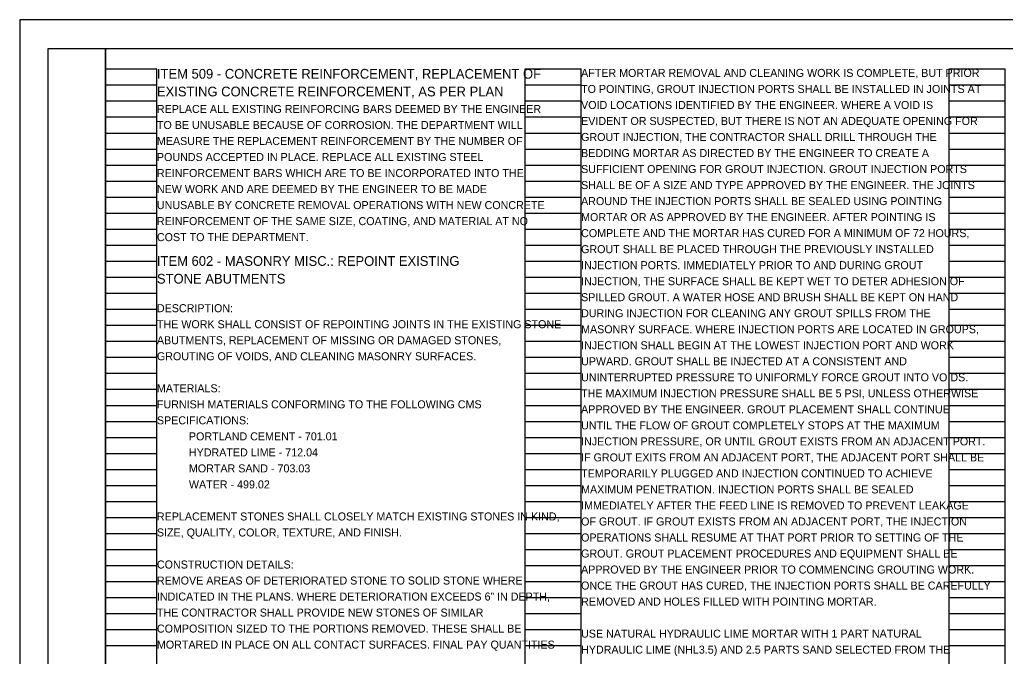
# Model space of a CAD drawing. Extents: x 0 to 59.1, y 0 to 43.6.
# Drawn here: x 0 to 17.24, y 10.87 to 22 of the extents above; entities that cross this region are included whole.
import ezdxf

# ---------------------------------------------------------------- set-up
doc = ezdxf.new("R2010")
doc.units = 0
for name, color, linetype in [('BR_P_Gen_Text', 7, 'Continuous'), ('SH_Border', 7, 'Continuous'), ('SH_Cut_Line', 7, 'Continuous'), ('SH_Data', 7, 'Continuous'), ('SH_Text', 7, 'Continuous')]:
    doc.layers.add(name, color=color, linetype=linetype)

msp = doc.modelspace()

# ---------------------------------------------------------------- linework, layer by layer
at = {"layer": 'SH_Border'}
for points in [[(0.5, 21.5), (1.5, 21.5), (1.5, 0.5), (0.5, 0.5)], [(1.5, 21.5), (33.5, 21.5), (33.5, 0.5), (1.5, 0.5)]]:
    msp.add_lwpolyline(points, close=True, dxfattribs=at)
at = {"layer": 'SH_Cut_Line'}
msp.add_lwpolyline([(0, 0), (34, 0), (34, 22), (0, 22)], close=True, dxfattribs=at)
at = {"layer": 'SH_Data'}
for p, q in [((1.5, 0.98), (1.5, 21.14)), ((1.5, 21.14), (2.4, 21.14)), ((2.4, 0.98), (2.4, 21.14)), ((8.84, 0.98), (8.84, 21.14)), ((8.84, 21.14), (9.82, 21.14)), ((9.82, 0.98), (9.82, 21.14)), ((16.26, 0.98), (16.26, 21.14)), ((16.26, 21.14), (17.24, 21.14)), ((17.24, 0.98), (17.24, 21.14)), ((1.5, 20.86), (2.4, 20.86)), ((8.84, 20.86), (9.82, 20.86)), ((16.26, 20.86), (17.24, 20.86)), ((1.5, 20.58), (2.4, 20.58)), ((8.84, 20.58), (9.82, 20.58)), ((16.26, 20.58), (17.24, 20.58)), ((1.5, 20.3), (2.4, 20.3)), ((8.84, 20.3), (9.82, 20.3)), ((16.26, 20.3), (17.24, 20.3)), ((1.5, 20.02), (2.4, 20.02)), ((8.84, 20.02), (9.82, 20.02)), ((16.26, 20.02), (17.24, 20.02)), ((1.5, 19.74), (2.4, 19.74)), ((8.84, 19.74), (9.82, 19.74)), ((16.26, 19.74), (17.24, 19.74)), ((1.5, 19.46), (2.4, 19.46)), ((8.84, 19.46), (9.82, 19.46)), ((16.26, 19.46), (17.24, 19.46)), ((1.5, 19.18), (2.4, 19.18)), ((8.84, 19.18), (9.82, 19.18)), ((16.26, 19.18), (17.24, 19.18)), ((1.5, 18.9), (2.4, 18.9)), ((8.84, 18.9), (9.82, 18.9)), ((16.26, 18.9), (17.24, 18.9)), ((1.5, 18.62), (2.4, 18.62)), ((8.84, 18.62), (9.82, 18.62)), ((16.26, 18.62), (17.24, 18.62)), ((1.5, 18.34), (2.4, 18.34)), ((8.84, 18.34), (9.82, 18.34)), ((16.26, 18.34), (17.24, 18.34)), ((1.5, 18.06), (2.4, 18.06)), ((8.84, 18.06), (9.82, 18.06)), ((16.26, 18.06), (17.24, 18.06)), ((1.5, 17.78), (2.4, 17.78)), ((8.84, 17.78), (9.82, 17.78)), ((16.26, 17.78), (17.24, 17.78)), ((1.5, 17.5), (2.4, 17.5)), ((8.84, 17.5), (9.82, 17.5)), ((16.26, 17.5), (17.24, 17.5)), ((1.5, 17.22), (2.4, 17.22)), ((8.84, 17.22), (9.82, 17.22)), ((16.26, 17.22), (17.24, 17.22)), ((1.5, 16.94), (2.4, 16.94)), ((8.84, 16.94), (9.82, 16.94)), ((16.26, 16.94), (17.24, 16.94)), ((1.5, 16.66), (2.4, 16.66)), ((8.84, 16.66), (9.82, 16.66)), ((16.26, 16.66), (17.24, 16.66)), ((1.5, 16.38), (2.4, 16.38)), ((8.84, 16.38), (9.82, 16.38)), ((16.26, 16.38), (17.24, 16.38)), ((1.5, 16.1), (2.4, 16.1)), ((8.84, 16.1), (9.82, 16.1)), ((16.26, 16.1), (17.24, 16.1)), ((1.5, 15.82), (2.4, 15.82)), ((8.84, 15.82), (9.82, 15.82)), ((16.26, 15.82), (17.24, 15.82)), ((1.5, 15.54), (2.4, 15.54)), ((8.84, 15.54), (9.82, 15.54)), ((16.26, 15.54), (17.24, 15.54)), ((1.5, 15.26), (2.4, 15.26)), ((8.84, 15.26), (9.82, 15.26)), ((16.26, 15.26), (17.24, 15.26)), ((1.5, 14.98), (2.4, 14.98)), ((8.84, 14.98), (9.82, 14.98)), ((16.26, 14.98), (17.24, 14.98)), ((1.5, 14.7), (2.4, 14.7)), ((8.84, 14.7), (9.82, 14.7)), ((16.26, 14.7), (17.24, 14.7)), ((1.5, 14.42), (2.4, 14.42)), ((8.84, 14.42), (9.82, 14.42)), ((16.26, 14.42), (17.24, 14.42)), ((1.5, 14.14), (2.4, 14.14)), ((8.84, 14.14), (9.82, 14.14)), ((16.26, 14.14), (17.24, 14.14)), ((1.5, 13.86), (2.4, 13.86)), ((8.84, 13.86), (9.82, 13.86)), ((16.26, 13.86), (17.24, 13.86)), ((1.5, 13.58), (2.4, 13.58)), ((8.84, 13.58), (9.82, 13.58)), ((16.26, 13.58), (17.24, 13.58)), ((1.5, 13.3), (2.4, 13.3)), ((8.84, 13.3), (9.82, 13.3)), ((16.26, 13.3), (17.24, 13.3)), ((1.5, 13.02), (2.4, 13.02)), ((8.84, 13.02), (9.82, 13.02)), ((16.26, 13.02), (17.24, 13.02)), ((1.5, 12.74), (2.4, 12.74)), ((8.84, 12.74), (9.82, 12.74)), ((16.26, 12.74), (17.24, 12.74)), ((1.5, 12.46), (2.4, 12.46)), ((8.84, 12.46), (9.82, 12.46)), ((16.26, 12.46), (17.24, 12.46)), ((1.5, 12.18), (2.4, 12.18)), ((8.84, 12.18), (9.82, 12.18)), ((16.26, 12.18), (17.24, 12.18)), ((1.5, 11.9), (2.4, 11.9)), ((8.84, 11.9), (9.82, 11.9)), ((16.26, 11.9), (17.24, 11.9)), ((1.5, 11.62), (2.4, 11.62)), ((8.84, 11.62), (9.82, 11.62)), ((16.26, 11.62), (17.24, 11.62)), ((1.5, 11.34), (2.4, 11.34)), ((8.84, 11.34), (9.82, 11.34)), ((16.26, 11.34), (17.24, 11.34)), ((1.5, 11.06), (2.4, 11.06)), ((8.84, 11.06), (9.82, 11.06)), ((16.26, 11.06), (17.24, 11.06))]:
    msp.add_line(p, q, dxfattribs=at)

# ---------------------------------------------------------------- texts
at = {"layer": 'BR_P_Gen_Text'}
for s, height, p in [('ITEM 509 - CONCRETE REINFORCEMENT, REPLACEMENT OF', 0.17, (2.4, 20.97)), ('EXISTING CONCRETE REINFORCEMENT, AS PER PLAN', 0.17, (2.4, 20.66)), ('REPLACE ALL EXISTING REINFORCING BARS DEEMED BY THE ENGINEER ', 0.14, (2.4, 20.37)), ('TO BE UNUSABLE BECAUSE OF CORROSION. THE DEPARTMENT WILL ', 0.14, (2.4, 20.09)), ('MEASURE THE REPLACEMENT REINFORCEMENT BY THE NUMBER OF ', 0.14, (2.4, 19.81)), ('POUNDS ACCEPTED IN PLACE. REPLACE ALL EXISTING STEEL ', 0.14, (2.4, 19.53)), ('REINFORCEMENT BARS WHICH ARE TO BE INCORPORATED INTO THE ', 0.14, (2.4, 19.25)), ('NEW WORK AND ARE DEEMED BY THE ENGINEER TO BE MADE ', 0.14, (2.4, 18.97)), ('UNUSABLE BY CONCRETE REMOVAL OPERATIONS WITH NEW CONCRETE ', 0.14, (2.4, 18.69)), ('REINFORCEMENT OF THE SAME SIZE, COATING, AND MATERIAL AT NO ', 0.14, (2.4, 18.41)), ('COST TO THE DEPARTMENT.', 0.14, (2.4, 18.13))]:
    msp.add_text(s, height=height, dxfattribs=at).set_placement(p)
at = {"layer": 'SH_Text'}
for s, height, p in [('AFTER MORTAR REMOVAL AND CLEANING WORK IS COMPLETE, BUT PRIOR ', 0.14, (9.82, 21)), ('TO POINTING, GROUT INJECTION PORTS SHALL BE INSTALLED IN JOINTS AT ', 0.14, (9.82, 20.72)), ('VOID LOCATIONS IDENTIFIED BY THE ENGINEER. WHERE A VOID IS ', 0.14, (9.82, 20.44)), ('EVIDENT OR SUSPECTED, BUT THERE IS NOT AN ADEQUATE OPENING FOR ', 0.14, (9.82, 20.16)), ('GROUT INJECTION, THE CONTRACTOR SHALL DRILL THROUGH THE ', 0.14, (9.82, 19.88)), ('BEDDING MORTAR AS DIRECTED BY THE ENGINEER TO CREATE A ', 0.14, (9.82, 19.6)), ('SUFFICIENT OPENING FOR GROUT INJECTION. GROUT INJECTION PORTS ', 0.14, (9.82, 19.32)), ('SHALL BE OF A SIZE AND TYPE APPROVED BY THE ENGINEER. THE JOINTS ', 0.14, (9.82, 19.04)), ('AROUND THE INJECTION PORTS SHALL BE SEALED USING POINTING ', 0.14, (9.82, 18.76)), ('MORTAR OR AS APPROVED BY THE ENGINEER. AFTER POINTING IS ', 0.14, (9.82, 18.48)), ('COMPLETE AND THE MORTAR HAS CURED FOR A MINIMUM OF 72 HOURS, ', 0.14, (9.82, 18.2)), ('GROUT SHALL BE PLACED THROUGH THE PREVIOUSLY INSTALLED ', 0.14, (9.82, 17.92)), ('ITEM 602 - MASONRY MISC.: REPOINT EXISTING', 0.17, (2.4, 17.698)), ('INJECTION PORTS. IMMEDIATELY PRIOR TO AND DURING GROUT ', 0.14, (9.82, 17.64)), ('STONE ABUTMENTS', 0.17, (2.4, 17.388)), ('INJECTION, THE SURFACE SHALL BE KEPT WET TO DETER ADHESION OF ', 0.14, (9.82, 17.36)), ('SPILLED GROUT. A WATER HOSE AND BRUSH SHALL BE KEPT ON HAND ', 0.14, (9.82, 17.08)), ('DESCRIPTION:', 0.14, (2.4, 16.888)), ('DURING INJECTION FOR CLEANING ANY GROUT SPILLS FROM THE ', 0.14, (9.82, 16.8)), ('THE WORK SHALL CONSIST OF REPOINTING JOINTS IN THE EXISTING STONE ', 0.14, (2.4, 16.608)), ('MASONRY SURFACE. WHERE INJECTION PORTS ARE LOCATED IN GROUPS, ', 0.14, (9.82, 16.52)), ('ABUTMENTS, REPLACEMENT OF MISSING OR DAMAGED STONES, ', 0.14, (2.4, 16.328)), ('INJECTION SHALL BEGIN AT THE LOWEST INJECTION PORT AND WORK ', 0.14, (9.82, 16.24)), ('GROUTING OF VOIDS, AND CLEANING MASONRY SURFACES.', 0.14, (2.4, 16.048)), ('UPWARD. GROUT SHALL BE INJECTED AT A CONSISTENT AND ', 0.14, (9.82, 15.96)), ('UNINTERRUPTED PRESSURE TO UNIFORMLY FORCE GROUT INTO VOIDS. ', 0.14, (9.82, 15.68)), ('MATERIALS:', 0.14, (2.4, 15.488)), ('THE MAXIMUM INJECTION PRESSURE SHALL BE 5 PSI, UNLESS OTHERWISE ', 0.14, (9.82, 15.4)), ('FURNISH MATERIALS CONFORMING TO THE FOLLOWING CMS ', 0.14, (2.4, 15.208)), ('APPROVED BY THE ENGINEER. GROUT PLACEMENT SHALL CONTINUE ', 0.14, (9.82, 15.12)), ('SPECIFICATIONS:', 0.14, (2.4, 14.928)), ('UNTIL THE FLOW OF GROUT COMPLETELY STOPS AT THE MAXIMUM ', 0.14, (9.82, 14.84)), ('PORTLAND CEMENT - 701.01', 0.14, (2.96, 14.648)), ('INJECTION PRESSURE, OR UNTIL GROUT EXISTS FROM AN ADJACENT PORT. ', 0.14, (9.82, 14.56)), ('HYDRATED LIME - 712.04', 0.14, (2.96, 14.368)), ('IF GROUT EXITS FROM AN ADJACENT PORT, THE ADJACENT PORT SHALL BE ', 0.14, (9.82, 14.28)), ('MORTAR SAND - 703.03', 0.14, (2.96, 14.088)), ('TEMPORARILY PLUGGED AND INJECTION CONTINUED TO ACHIEVE ', 0.14, (9.82, 14)), ('WATER - 499.02', 0.14, (2.96, 13.808)), ('MAXIMUM PENETRATION. INJECTION PORTS SHALL BE SEALED ', 0.14, (9.82, 13.72)), ('IMMEDIATELY AFTER THE FEED LINE IS REMOVED TO PREVENT LEAKAGE ', 0.14, (9.82, 13.44)), ('REPLACEMENT STONES SHALL CLOSELY MATCH EXISTING STONES IN KIND, ', 0.14, (2.4, 13.248)), ('OF GROUT. IF GROUT EXISTS FROM AN ADJACENT PORT, THE INJECTION ', 0.14, (9.82, 13.16)), ('SIZE, QUALITY, COLOR, TEXTURE, AND FINISH.', 0.14, (2.4, 12.968)), ('OPERATIONS SHALL RESUME AT THAT PORT PRIOR TO SETTING OF THE ', 0.14, (9.82, 12.88)), ('GROUT. GROUT PLACEMENT PROCEDURES AND EQUIPMENT SHALL BE ', 0.14, (9.82, 12.6)), ('CONSTRUCTION DETAILS:', 0.14, (2.4, 12.408)), ('APPROVED BY THE ENGINEER PRIOR TO COMMENCING GROUTING WORK. ', 0.14, (9.82, 12.32)), ('REMOVE AREAS OF DETERIORATED STONE TO SOLID STONE WHERE ', 0.14, (2.4, 12.128)), ('ONCE THE GROUT HAS CURED, THE INJECTION PORTS SHALL BE CAREFULLY ', 0.14, (9.82, 12.04)), ('INDICATED IN THE PLANS. WHERE DETERIORATION EXCEEDS 6” IN DEPTH, ', 0.14, (2.4, 11.848)), ('REMOVED AND HOLES FILLED WITH POINTING MORTAR.', 0.14, (9.82, 11.76)), ('THE CONTRACTOR SHALL PROVIDE NEW STONES OF SIMILAR ', 0.14, (2.4, 11.568)), ('COMPOSITION SIZED TO THE PORTIONS REMOVED. THESE SHALL BE ', 0.14, (2.4, 11.288)), ('USE NATURAL HYDRAULIC LIME MORTAR WITH 1 PART NATURAL ', 0.14, (9.82, 11.2)), ('MORTARED IN PLACE ON ALL CONTACT SURFACES. FINAL PAY QUANTITIES ', 0.14, (2.4, 11.008)), ('HYDRAULIC LIME (NHL3.5) AND 2.5 PARTS SAND SELECTED FROM THE ', 0.14, (9.82, 10.92))]:
    msp.add_text(s, height=height, dxfattribs=at).set_placement(p)

doc.saveas('drawing.dxf')
